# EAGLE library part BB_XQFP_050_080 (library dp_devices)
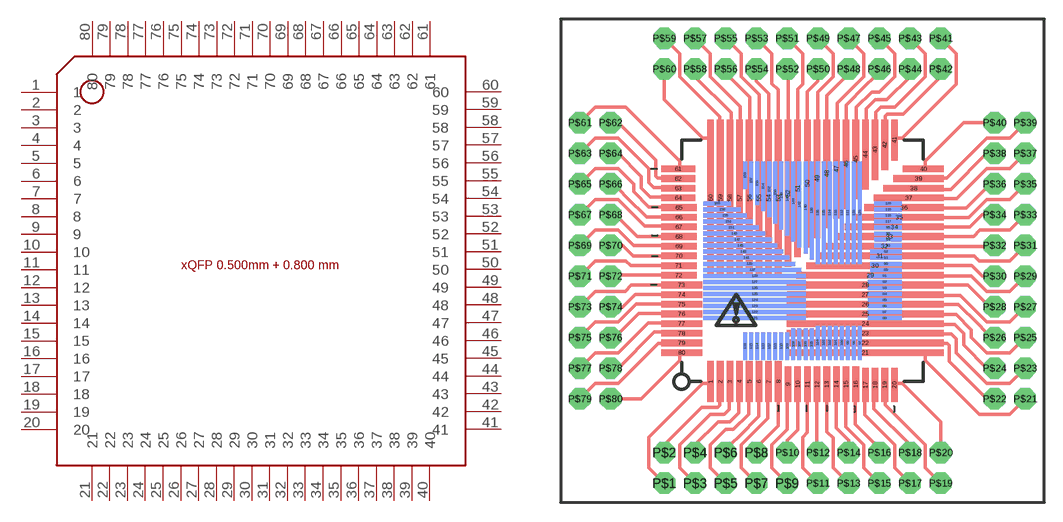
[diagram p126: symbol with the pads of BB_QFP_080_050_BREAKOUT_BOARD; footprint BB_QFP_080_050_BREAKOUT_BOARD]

Designator prefix IC

## BB_XQFP_050_080  [BB_QFP_080_050_BREAKOUT_BOARD]
1  1
2  2
3  3
4  4
5  5
6  6
7  7
8  8
9  9
10  10
11  11
12  12
13  13
14  14
15  15
16  16
17  17
18  18
19  19
20  20
21  21
22  22
23  23
24  24
25  25
26  26
27  27
28  28
29  29
30  30
31  31
32  32
33  33
34  34
35  35
36  36
37  37
38  38
39  39
40  40
41  41
42  42
43  43
44  44
45  45
46  46
47  47
48  48
49  49
50  50
51  51
52  52
53  53
54  54
55  55
56  56
57  57
58  58
59  59
60  60
61  61
62  62
63  63
64  64
65  65
66  66
67  67
68  68
69  69
70  70
71  71
72  72
73  73
74  74
75  75
76  76
77  77
78  78
79  79
80  80

## Footprint BB_QFP_080_050_BREAKOUT_BOARD (pad centres in mm)
QFP 0.5 mm pitch 32p (5mm sq) 48p (7mm sq) 64p (10mm sq) 80p (12mm sq) QFP 0.8 mm pitch 32p (7mm sq) 44p (10mm sq) 64p (14mm sq) 80p (16.5mm sq) CC-BY-SA
smd 0.55 x 3.405: 1 -7.6,-9.998; 2 -6.8,-9.998; 3 -6,-9.998; 4 -5.2,-9.998; 5 -4.4,-9.998; 6 -3.6,-9.998; 7 -2.8,-9.998; 8 -2,-9.998; 41 7.6,9.997
smd 0.55 x 2.95: 9 -1.2,-10.225; 10 -0.4,-10.225; 11 0.4,-10.225; 12 1.2,-10.225; 13 2,-10.225; 14 2.8,-10.225; 15 3.6,-10.225; 16 4.4,-10.225
smd 0.55 x 2.85: 17 5.2,-10.275; 18 6,-10.275; 19 6.8,-10.275; 20 7.6,-10.275
smd 13.005 x 0.55: 21 5.197,-7.6; 22 5.197,-6.8; 23 5.197,-6; 24 5.197,-5.2; 25 5.197,-4.4; 26 5.197,-3.6; 27 5.197,-2.8; 28 5.197,-2
smd 12.205 x 0.55: 29 5.597,-1.2
smd 11.405 x 0.55: 30 5.997,-0.4
smd 10.605 x 0.55: 31 6.397,0.4
smd 9.805 x 0.55: 32 6.797,1.2
smd 9.005 x 0.55: 33 7.197,2
smd 8.205 x 0.55: 34 7.597,2.8
smd 7.405 x 0.55: 35 7.997,3.6
smd 6.605 x 0.55: 36 8.397,4.4
smd 5.805 x 0.55: 37 8.797,5.2
smd 5.005 x 0.55: 38 9.197,6
smd 4.205 x 0.55: 39 9.597,6.8
smd 3.405 x 0.55: 40 9.997,7.6; 73 -9.998,-2; 74 -9.998,-2.8; 75 -9.998,-3.6; 76 -9.998,-4.4; 77 -9.998,-5.2; 78 -9.998,-6; 79 -9.998,-6.8; 80 -9.998,-7.6
smd 0.55 x 4.205: 42 6.8,9.597
smd 0.55 x 5.005: 43 6,9.197
smd 0.55 x 5.805: 44 5.2,8.797
smd 0.55 x 6.605: 45 4.4,8.397
smd 0.55 x 7.405: 46 3.6,7.997
smd 0.55 x 8.205: 47 2.8,7.597
smd 0.55 x 9.005: 48 2,7.197
smd 0.55 x 9.805: 49 1.2,6.797
smd 0.55 x 10.605: 50 0.4,6.397
smd 0.55 x 11.405: 51 -0.4,5.997
smd 0.55 x 12.205: 52 -1.2,5.597
smd 0.55 x 13.005: 53 -2,5.198; 54 -2.8,5.198; 55 -3.6,5.198; 56 -4.4,5.198; 57 -5.2,5.198; 58 -6,5.198; 59 -6.8,5.198; 60 -7.6,5.198
smd 2.85 x 0.55: 61 -10.275,7.6; 62 -10.275,6.8; 63 -10.275,6; 64 -10.275,5.2
smd 2.95 x 0.55: 65 -10.225,4.4; 66 -10.225,3.6; 67 -10.225,2.8; 68 -10.225,2; 69 -10.225,1.2; 70 -10.225,0.4; 71 -10.225,-0.4; 72 -10.225,-1.2
smd 2.824 x 0.33 bottom: 81 6.788,-1.25; 82 6.788,-1.75; 83 6.788,-2.25; 84 6.788,-2.75; 85 6.788,-3.25; 86 6.788,-3.75; 87 6.788,-4.25; 88 6.788,-4.75
smd 2.6 x 0.33 bottom: 89 6.9,-0.75; 90 6.9,-0.25; 91 6.9,0.25; 92 6.9,0.75
smd 2.25 x 0.33 bottom: 93 7.075,1.25; 94 7.075,1.75; 95 7.075,2.75; 96 7.075,2.25; 117 7.075,3.25; 118 7.075,3.75; 119 7.075,4.25; 120 7.075,4.75; 160 -7.075,4.75
smd 0.33 x 2.824 bottom: 97 4.75,-6.788; 98 4.25,-6.788; 99 3.75,-6.788; 100 3.25,-6.788; 101 2.75,-6.788; 102 2.25,-6.788; 103 1.75,-6.788; 104 1.25,-6.788
smd 0.33 x 2.6 bottom: 105 0.75,-6.9; 106 0.25,-6.9; 107 -0.25,-6.9; 108 -0.75,-6.9
smd 0.33 x 2.25 bottom: 109 -1.25,-7.075; 110 -1.75,-7.075; 111 -2.25,-7.075; 112 -2.75,-7.075; 113 -3.25,-7.075; 114 -3.75,-7.075; 115 -4.25,-7.075; 116 -4.75,-7.075; 159 -4.75,7.075
smd 8.47 x 0.33 bottom: 121 -3.965,-4.75; 122 -3.965,-4.25; 123 -3.965,-3.75; 124 -3.965,-3.25; 125 -3.965,-2.75; 126 -3.965,-2.25; 127 -3.965,-1.75; 128 -3.965,-1.25
smd 0.33 x 8.47 bottom: 129 4.75,3.965; 130 4.25,3.965; 131 3.75,3.965; 132 3.25,3.965; 133 2.75,3.965; 134 2.25,3.965; 135 1.75,3.965; 136 1.25,3.965
smd 8.1 x 0.33 bottom: 137 -4.15,-0.75
smd 0.33 x 8.1 bottom: 138 0.75,4.15
smd 7.6 x 0.33 bottom: 139 -4.4,-0.25
smd 0.33 x 7.6 bottom: 140 0.25,4.4
smd 7.1 x 0.33 bottom: 141 -4.65,0.25
smd 0.33 x 7.1 bottom: 142 -0.25,4.65
smd 6.6 x 0.33 bottom: 143 -4.9,0.75
smd 0.33 x 6.6 bottom: 144 -0.75,4.9
smd 6.1 x 0.33 bottom: 145 -5.15,1.25
smd 0.33 x 6.1 bottom: 146 -1.25,5.15
smd 5.6 x 0.33 bottom: 147 -5.4,1.75
smd 0.33 x 5.6 bottom: 148 -1.75,5.4
smd 5.1 x 0.33 bottom: 149 -5.65,2.25
smd 0.33 x 5.1 bottom: 150 -2.25,5.65
smd 4.6 x 0.33 bottom: 151 -5.9,2.75
smd 0.33 x 4.6 bottom: 152 -2.75,5.9
smd 4.1 x 0.33 bottom: 153 -6.15,3.25
smd 0.33 x 4.1 bottom: 154 -3.25,6.15
smd 3.6 x 0.33 bottom: 155 -6.4,3.75
smd 0.33 x 3.6 bottom: 156 -3.75,6.4
smd 0.33 x 3.1 bottom: 157 -4.25,6.65
smd 3.1 x 0.33 bottom: 158 -6.65,4.25
drill 1.016 pad 1.778 octagon: P$1 -11.43,-18.415; P$2 -11.43,-15.875; P$3 -8.89,-18.415; P$4 -8.89,-15.875; P$5 -6.35,-18.415; P$6 -6.35,-15.875; P$7 -3.81,-18.415; P$8 -3.81,-15.875; P$9 -1.27,-18.415; P$10 -1.27,-15.875; P$11 1.27,-18.415; P$12 1.27,-15.875; P$13 3.81,-18.415; P$14 3.81,-15.875; P$15 6.35,-18.415; P$16 6.35,-15.875; P$17 8.89,-18.415; P$18 8.89,-15.875; P$19 11.43,-18.415; P$20 11.43,-15.875; P$21 18.415,-11.43; P$22 15.875,-11.43; P$23 18.415,-8.89; P$24 15.875,-8.89; P$25 18.415,-6.35; P$26 15.875,-6.35; P$27 18.415,-3.81; P$28 15.875,-3.81; P$29 18.415,-1.27; P$30 15.875,-1.27; P$31 18.415,1.27; P$32 15.875,1.27; P$33 18.415,3.81; P$34 15.875,3.81; P$35 18.415,6.35; P$36 15.875,6.35; P$37 18.415,8.89; P$38 15.875,8.89; P$39 18.415,11.43; P$40 15.875,11.43; P$41 11.43,18.415; P$42 11.43,15.875; P$43 8.89,18.415; P$44 8.89,15.875; P$45 6.35,18.415; P$46 6.35,15.875; P$47 3.81,18.415; P$48 3.81,15.875; P$49 1.27,18.415; P$50 1.27,15.875; P$51 -1.27,18.415; P$52 -1.27,15.875; P$53 -3.81,18.415; P$54 -3.81,15.875; P$55 -6.35,18.415; P$56 -6.35,15.875; P$57 -8.89,18.415; P$58 -8.89,15.875; P$59 -11.43,18.415; P$60 -11.43,15.875; P$61 -18.415,11.43; P$62 -15.875,11.43; P$63 -18.415,8.89; P$64 -15.875,8.89; P$65 -18.415,6.35; P$66 -15.875,6.35; P$67 -18.415,3.81; P$68 -15.875,3.81; P$69 -18.415,1.27; P$70 -15.875,1.27; P$71 -18.415,-1.27; P$72 -15.875,-1.27; P$73 -18.415,-3.81; P$74 -15.875,-3.81; P$75 -18.415,-6.35; P$76 -15.875,-6.35; P$77 -18.415,-8.89; P$78 -15.875,-8.89; P$79 -18.415,-11.43; P$80 -15.875,-11.43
